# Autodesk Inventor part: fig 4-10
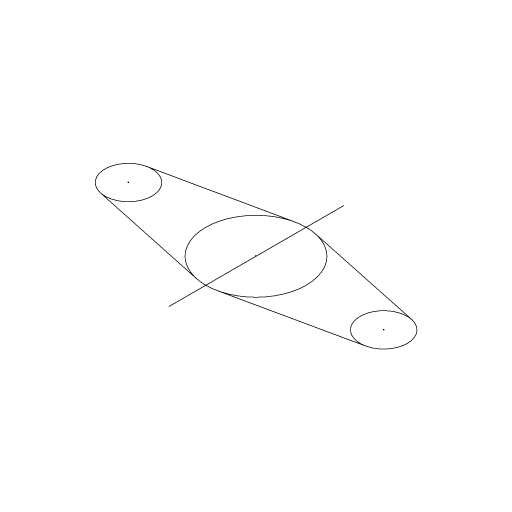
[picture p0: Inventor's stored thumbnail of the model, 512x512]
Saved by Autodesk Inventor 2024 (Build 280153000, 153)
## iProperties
Created: 2005-02
Part Number: fig 4-10
Document SubType Name: Modeling
Designer: CADCIM
Manufacturer: Standard
Standards Organization: Custom
Density: 1 g/cm^3
Material: Generic
Appearance: Default
Author: CADCIM
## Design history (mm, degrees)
sketch "Sketch1"
  geometry: L1 (-33.874, 5.844)-(-2.722, 12.469); L2 (-33.884, -5.902)-(-2.745, -12.585); L3 (-0.057, 22.288)-(-0.057, -22.318); L4 (33.759, 5.844)-(2.608, 12.469); L5 (33.77, -5.902)-(2.63, -12.585); A1 r 12.81 centre (-0.057, -0.06) between (-2.722, 12.469) and (-2.745, -12.585); A2 r 6.006 centre (-32.624, -0.03) between (-33.874, 5.844) and (-33.884, -5.902); A3 r 6.006 centre (32.51, -0.03) between (33.759, 5.844) and (33.77, -5.902)
  constraints: 10 end point, 6 point on circle, 5 symmetric about line, 4 tangent, 3 centre point, 1 vertical, 2 other
